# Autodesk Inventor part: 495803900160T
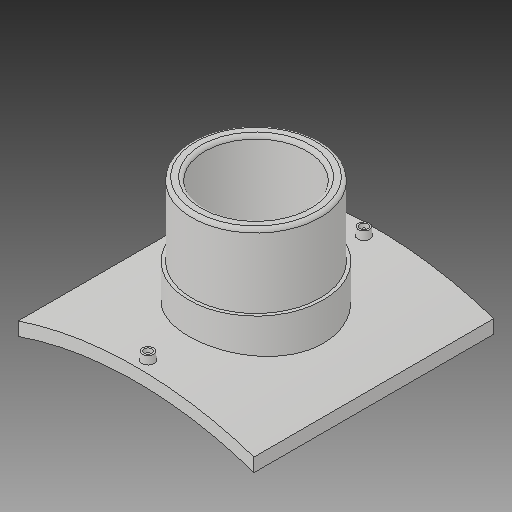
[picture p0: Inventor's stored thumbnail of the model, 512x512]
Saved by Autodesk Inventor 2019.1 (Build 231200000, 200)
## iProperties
Created: 2017-10
Part Number: 495803900160T
Material: Generic
Description: PLASSON BRANCH SADDLE  900x160
Document SubType Name: Modeling
Designer: KIM
Mass: 2754.05 g
Surface Area: 3037.44 cm^2
Volume: 2754.05 cm^3
Density: 1 g/cm^3
Appearance: Default
Author: KIM
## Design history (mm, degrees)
derived "495803.ipt"
feature "Solid1::495803.ipt"
tag "TaggingFeature1"
body "Solid1"
other parameters: "d1" = 16, "d2" = 295, "d4" = 0, "d12" = 475.6, "d13" = 14, "d14" = 135, "d16" = 5 deg, "d18" = 4, "d19" = 14, "d20" = 0, "d21" = 3, "d22" = 0, "d23" = 597, "d24" = 168, "d25" = 16, "d26" = 128, "d28" = 0, "d29" = 9.6, "d31" = 0, "d32" = 65.5, "d33" = 0, "d34" = 9, "d37" = 91.7, "d38" = 0, "d39" = 4.5, "B_" = 295, "H_" = 131, "x_" = 16, "D_" = 16
